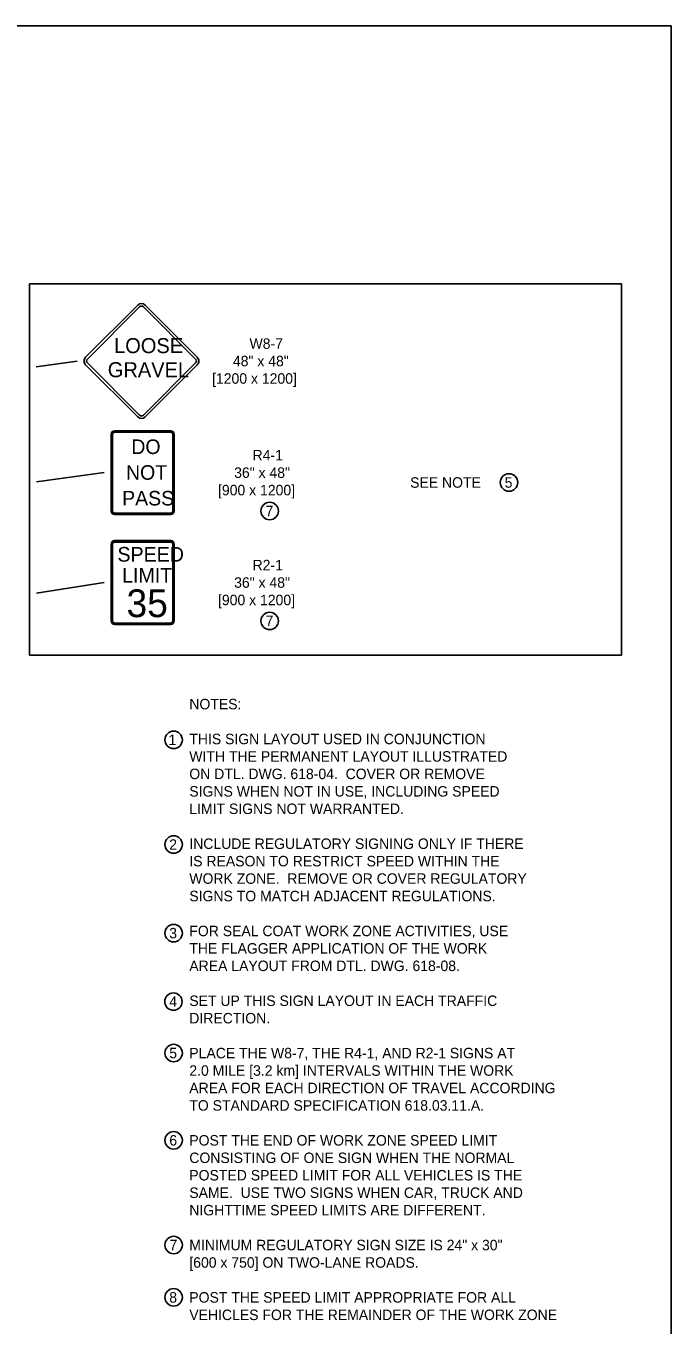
# Model space of a CAD drawing. Extents: x 49991.4 to 50021, y 49987.6 to 50011.4.
# Drawn here: x 50004.92 to 50008.61, y 50003.82 to 50011.26 of the extents above; entities that cross this region are included whole.
import ezdxf

# ---------------------------------------------------------------- set-up
doc = ezdxf.new("R2010")
doc.units = 0
for name, color, linetype in [('Level 1', 7, 'Continuous'), ('Level 2', 7, 'Continuous'), ('Level 3', 7, 'Continuous')]:
    doc.layers.add(name, color=color, linetype=linetype)

msp = doc.modelspace()

# ---------------------------------------------------------------- linework, layer by layer
at = {"layer": 'Level 1'}
for p, q in [((50005.2581, 50009.3642), (50005.557, 50009.663)), ((50005.5997, 50009.663), (50005.8985, 50009.3642)), ((50005.5671, 50009.6529), (50005.2682, 50009.3541)), ((50005.5671, 50009.6529), (50005.5671, 50009.6529)), ((50005.8884, 50009.3541), (50005.5896, 50009.6529)), ((50005.557, 50009.0226), (50005.2581, 50009.3215)), ((50005.2682, 50009.3316), (50005.5671, 50009.0327)), ((50005.5896, 50009.0327), (50005.8884, 50009.3316)), ((50005.8985, 50009.3215), (50005.5997, 50009.0226)), ((50005.4053, 50008.9231), (50005.4053, 50008.4831)), ((50005.4128, 50008.9231), (50005.4128, 50008.4831)), ((50005.7465, 50008.9431), (50005.424, 50008.9431)), ((50005.7465, 50008.9351), (50005.424, 50008.9351)), ((50005.7578, 50008.4831), (50005.7578, 50008.9231)), ((50005.7653, 50008.4831), (50005.7653, 50008.9231)), ((50005.424, 50008.4711), (50005.7465, 50008.4711)), ((50005.424, 50008.4631), (50005.7465, 50008.4631)), ((50005.4053, 50008.2934), (50005.4053, 50007.8534)), ((50005.4128, 50008.2934), (50005.4128, 50007.8534)), ((50005.7465, 50008.3134), (50005.424, 50008.3134)), ((50005.7465, 50008.3054), (50005.424, 50008.3054)), ((50005.7578, 50007.8534), (50005.7578, 50008.2934)), ((50005.7653, 50007.8534), (50005.7653, 50008.2934)), ((50005.424, 50007.8414), (50005.7465, 50007.8414)), ((50005.424, 50007.8334), (50005.7465, 50007.8334))]:
    msp.add_line(p, q, dxfattribs=at)
msp.add_lwpolyline([(50008.6146, 50011.2628), (50000.3356, 50011.2628), (50000.3356, 50000.0624), (50008.6146, 50000.0624)], close=True, dxfattribs=at)
for centre, radius, start, end in [((50005.5783, 50009.6416), 0.0302, 45.00008, 134.99993), ((50005.5783, 50009.6416), 0.0159, 45.00008, 134.99993), ((50005.2795, 50009.3427), 0.0302, 134.99993, 225.00008), ((50005.2795, 50009.3427), 0.0159, 134.99993, 225.00008), ((50005.8772, 50009.3427), 0.0159, 314.99993, 45.00007), ((50005.8772, 50009.3427), 0.0302, 314.99993, 45.00008), ((50005.5783, 50009.0439), 0.0302, 225.00007, 314.99993), ((50005.5783, 50009.0439), 0.0159, 225.00007, 314.99993)]:
    msp.add_arc(centre, radius, start, end, dxfattribs=at)
for centre, major_axis, start_param, end_param in [((50005.4242, 50008.923), (0, 0.02), 0, 1.570796), ((50005.4242, 50008.923), (0, 0.012), 0, 1.570796), ((50005.7467, 50008.923), (0, 0.02), 4.712389, 6.283185), ((50005.7467, 50008.923), (0, 0.012), 4.712389, 6.283185), ((50005.4242, 50008.483), (0, -0.02), 4.712389, 6.283185), ((50005.4242, 50008.483), (0, -0.012), 4.712389, 6.283185), ((50005.7467, 50008.483), (0, -0.02), 0, 1.570796), ((50005.7467, 50008.483), (0, -0.012), 0, 1.570796), ((50005.4241, 50008.2935), (0, 0.02), 0, 1.570796), ((50005.4241, 50008.2935), (0, 0.012), 0, 1.570796), ((50005.7466, 50008.2935), (0, 0.02), 4.712389, 6.283185), ((50005.7466, 50008.2935), (0, 0.012), 4.712389, 6.283185), ((50005.4241, 50007.8535), (0, -0.02), 4.712389, 6.283185), ((50005.4241, 50007.8535), (0, -0.012), 4.712389, 6.283185), ((50005.7466, 50007.8535), (0, -0.02), 0, 1.570796), ((50005.7466, 50007.8535), (0, -0.012), 0, 1.570796)]:
    msp.add_ellipse(centre, major_axis=major_axis, ratio=0.9375, start_param=start_param, end_param=end_param, dxfattribs=at)
at = {"layer": 'Level 2'}
for p, q in [((50004.9361, 50009.7847), (50008.3301, 50009.7847)), ((50004.9361, 50007.6578), (50004.9361, 50009.7847)), ((50008.3301, 50009.7847), (50008.3301, 50007.6578)), ((50004.9361, 50007.6578), (50008.3301, 50007.6578))]:
    msp.add_line(p, q, dxfattribs=at)
for centre in [(50007.6856, 50008.6467), (50006.3136, 50008.4831), (50006.3136, 50007.8534), (50005.7628, 50007.1719), (50005.7628, 50006.5719), (50005.7628, 50006.0641), (50005.7618, 50005.6719), (50005.7628, 50005.377), (50005.7628, 50004.877), (50005.7628, 50004.2767), (50005.7628, 50003.977)]:
    msp.add_circle(centre, 0.05, dxfattribs=at)
at = {"layer": 'Level 3'}
for p, q in [((50005.2093, 50009.3427), (50004.9757, 50009.3092)), ((50005.2493, 50009.3427), (50005.2493, 50009.3427)), ((50005.3653, 50008.7031), (50004.9761, 50008.6512)), ((50005.3653, 50008.0734), (50004.9764, 50008.0125))]:
    msp.add_line(p, q, dxfattribs=at)

# ---------------------------------------------------------------- texts
at = {"layer": 'Level 1'}
for s, height, p in [('LOOSE', 0.08598, (50005.4213, 50009.3879)), ('GRAVEL', 0.08598, (50005.3853, 50009.2501)), ('DO', 0.08352, (50005.5204, 50008.8099)), ('NOT', 0.08352, (50005.4898, 50008.6624)), ('PASS', 0.08352, (50005.4678, 50008.5149))]:
    msp.add_text(s, height=height, rotation=360, dxfattribs=at).set_placement(p)
for s, height, p in [('SPEED', 0.0841, (50005.4408, 50008.193)), ('LIMIT', 0.0841, (50005.4674, 50008.0729)), ('35', 0.15914, (50005.4929, 50007.8751))]:
    msp.add_text(s, height=height, dxfattribs=at).set_placement(p)
at = {"layer": 'Level 2'}
for s, p in [('W8-7', (50006.1979, 50009.4127)), ('48" x 48"', (50006.1028, 50009.3127)), ('[1200 x 1200]', (50005.9833, 50009.2127)), ('R4-1', (50006.2154, 50008.7731)), ('36" x 48"', (50006.1099, 50008.6731)), ('[900 x 1200]', (50006.0174, 50008.5731)), ('SEE NOTE ', (50007.1187, 50008.6167)), ('5', (50007.6607, 50008.6167)), ('7', (50006.2898, 50008.4531)), ('R2-1', (50006.2154, 50008.1434)), ('36" x 48"', (50006.1098, 50008.0434)), ('[900 x 1200]', (50006.0173, 50007.9434)), ('7', (50006.2898, 50007.8234)), ('NOTES:', (50005.8528, 50007.3468)), ('THIS SIGN LAYOUT USED IN CONJUNCTION', (50005.8528, 50007.1468)), ('1', (50005.733, 50007.1419)), ('WITH THE PERMANENT LAYOUT ILLUSTRATED', (50005.8528, 50007.0468)), ('ON DTL. DWG. 618-04.  COVER OR REMOVE', (50005.8528, 50006.9468)), ('SIGNS WHEN NOT IN USE, INCLUDING SPEED', (50005.8528, 50006.8468)), ('LIMIT SIGNS NOT WARRANTED.', (50005.8528, 50006.7468)), ('2', (50005.7376, 50006.5419)), ('INCLUDE REGULATORY SIGNING ONLY IF THERE', (50005.8528, 50006.5468)), ('IS REASON TO RESTRICT SPEED WITHIN THE ', (50005.8528, 50006.4468)), ('WORK ZONE.  REMOVE OR COVER REGULATORY ', (50005.8528, 50006.3468)), ('SIGNS TO MATCH ADJACENT REGULATIONS.', (50005.8528, 50006.2468)), ('3', (50005.7376, 50006.0341)), ('FOR SEAL COAT WORK ZONE ACTIVITIES, USE', (50005.8528, 50006.0468)), ('THE FLAGGER APPLICATION OF THE WORK', (50005.8528, 50005.9468)), ('AREA LAYOUT FROM DTL. DWG. 618-08.', (50005.8528, 50005.8468)), ('4', (50005.7379, 50005.6419)), ('SET UP THIS SIGN LAYOUT IN EACH TRAFFIC', (50005.8528, 50005.6468)), ('DIRECTION.', (50005.8528, 50005.5468)), ('5', (50005.7379, 50005.347)), ('PLACE THE W8-7, THE R4-1, AND R2-1 SIGNS AT', (50005.8528, 50005.3468)), ('2.0 MILE [3.2 km] INTERVALS WITHIN THE WORK ', (50005.8528, 50005.2468)), ('AREA FOR EACH DIRECTION OF TRAVEL ACCORDING', (50005.8528, 50005.1468)), ('TO STANDARD SPECIFICATION 618.03.11.A.', (50005.8528, 50005.0468)), ('6', (50005.7383, 50004.847)), ('POST THE END OF WORK ZONE SPEED LIMIT ', (50005.8528, 50004.8468)), ('CONSISTING OF ONE SIGN WHEN THE NORMAL', (50005.8528, 50004.7468)), ('POSTED SPEED LIMIT FOR ALL VEHICLES IS THE ', (50005.8528, 50004.6468)), ('SAME.  USE TWO SIGNS WHEN CAR, TRUCK AND ', (50005.8528, 50004.5468)), ('NIGHTTIME SPEED LIMITS ARE DIFFERENT.', (50005.8528, 50004.4468)), ('7', (50005.739, 50004.2467)), ('MINIMUM REGULATORY SIGN SIZE IS 24" x 30"', (50005.8528, 50004.2468)), ('[600 x 750] ON TWO-LANE ROADS.', (50005.8528, 50004.1468)), ('8', (50005.7378, 50003.947)), ('POST THE SPEED LIMIT APPROPRIATE FOR ALL ', (50005.8528, 50003.9468)), ('VEHICLES FOR THE REMAINDER OF THE WORK ZONE', (50005.8528, 50003.8468))]:
    msp.add_text(s, height=0.06, dxfattribs=at).set_placement(p)

doc.saveas('drawing.dxf')
